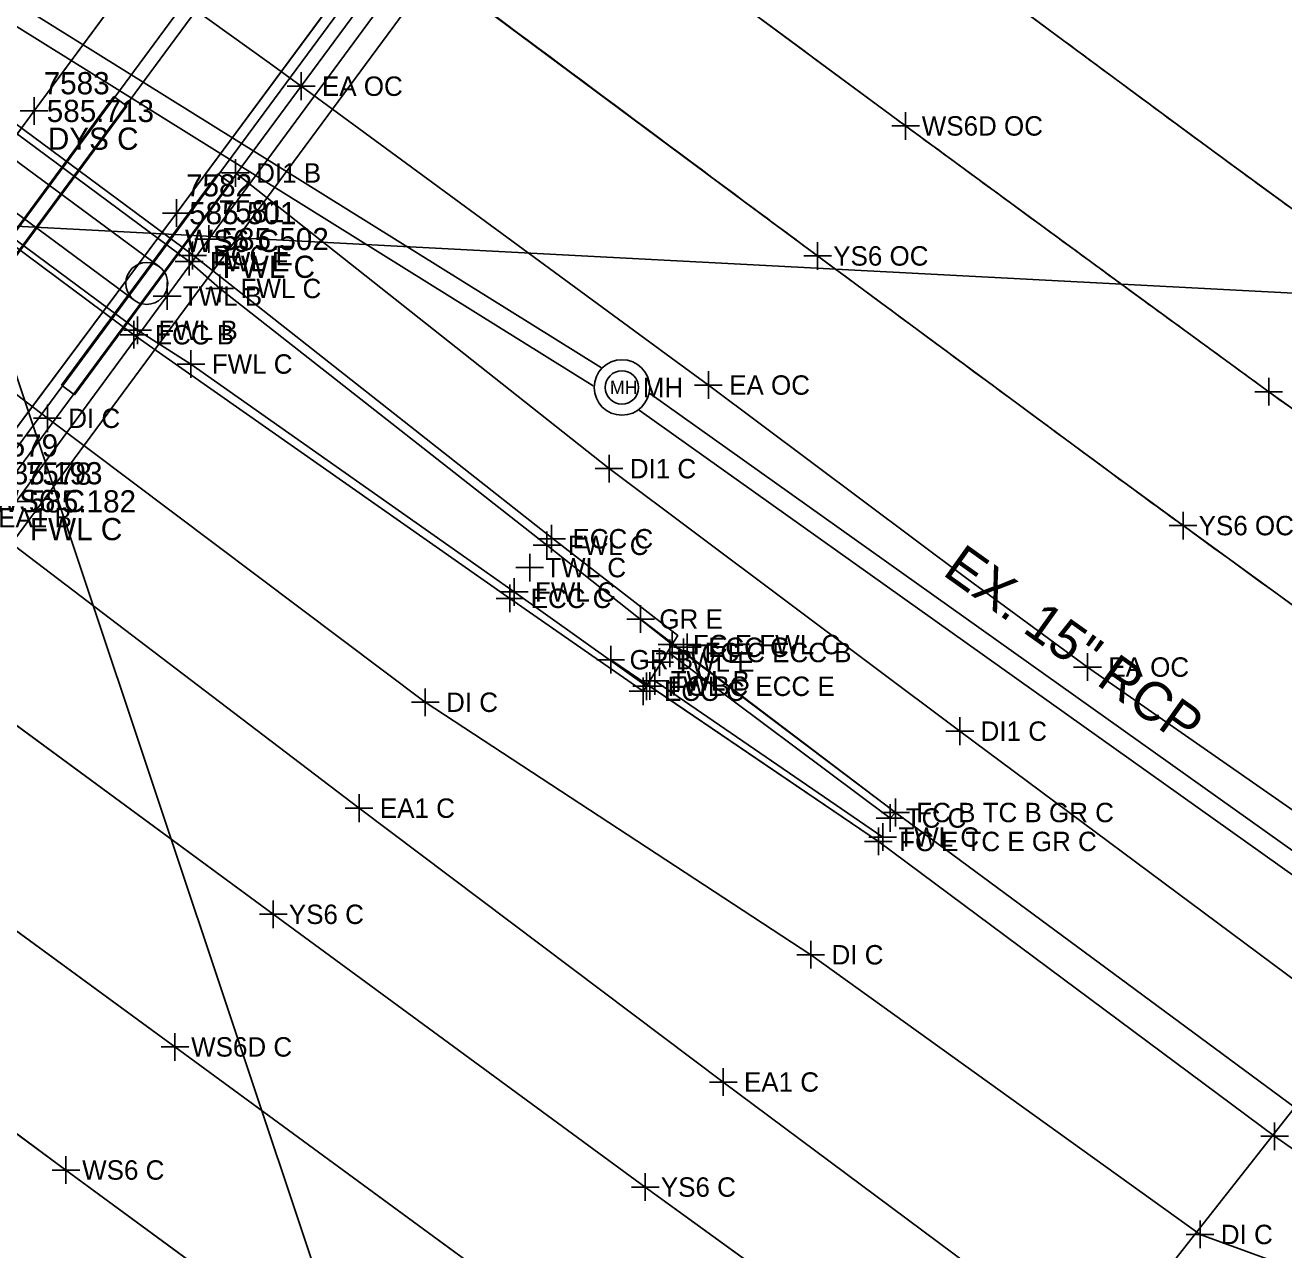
# Model space of a CAD drawing. Extents: x 1324236 to 1326110, y 459090 to 460782.
# Drawn here: x 1325137.7 to 1325228.5, y 459976.5 to 460064.8 of the extents above; entities that cross this region are included whole.
import ezdxf

# ---------------------------------------------------------------- set-up
doc = ezdxf.new("R2010")
doc.units = 0
for name, color, linetype in [('BD_X_Building', 7, 'Continuous'), ('BD_X_Canopy', 7, 'Continuous'), ('DR_X_Ditch', 7, 'Continuous'), ('DR_X_Drive_Pipe', 7, 'Continuous'), ('DR_X_Storm_Sewer', 7, 'Continuous'), ('DT_X_Contour_Text', 7, 'Continuous'), ('DT_X_Terrain_Boundary', 7, 'Continuous'), ('DT_X_Void', 7, 'Continuous'), ('DV_X_Property_Line', 7, 'Continuous'), ('E-RW-ODOT', 7, 'Continuous'), ('LT_X_Poles', 7, 'Continuous'), ('PM_X_Edge_Line', 7, 'Continuous'), ('PM_X_Lane_Line', 7, 'Continuous'), ('PM_X_Parking_Lot_Stall', 7, 'Continuous'), ('PV_X_Shoulder', 7, 'Continuous'), ('RD_X_Concrete_Barrier', 7, 'Continuous'), ('RW_X_CL', 7, 'Continuous'), ('RW_X_Esmt_SH', 7, 'Continuous'), ('UT_X_Gas', 7, 'Continuous'), ('UT_X_Telecom', 7, 'Continuous'), ('VG_X_Flower_Bed', 7, 'Continuous'), ('VG_X_Tree_Line_Lt', 7, 'Continuous')]:
    doc.layers.add(name, color=color, linetype=linetype)

msp = doc.modelspace()

# ---------------------------------------------------------------- linework, layer by layer
at = {"layer": 'BD_X_Building'}
for p, q in [((1325067.482, 459955.828), (1325213.75, 460153.784)), ((1325068.286, 459955.234), (1325214.554, 460153.19)), ((1325074.995, 459950.304), (1325221.27, 460148.255)), ((1325075.8, 459949.71), (1325222.074, 460147.66))]:
    msp.add_line(p, q, dxfattribs=at)
at = {"layer": 'BD_X_Canopy'}
for points in [[(1325045.611, 459932.876), (1325057.851, 459949.53), (1325064.246, 459958.184), (1325079.335, 459978.633), (1325094.378, 459999.012), (1325110.069, 460020.457), (1325125.333, 460040.949), (1325138.348, 460058.621), (1325153.722, 460079.38), (1325168.359, 460099.091), (1325182.797, 460118.646), (1325197.597, 460138.568), (1325210.747, 460156.012)], [(1325148.737, 460096.817), (1325164.239, 460084.921), (1325164.239, 460084.921), (1325170.939, 460079.893), (1325170.939, 460079.893), (1325200.178, 460058.291), (1325200.178, 460058.291), (1325201.195, 460057.542), (1325201.195, 460057.542), (1325216.328, 460046.448), (1325216.328, 460046.448), (1325227.38, 460038.385), (1325227.38, 460038.385), (1325239.571, 460029.695)], [(1325098.234, 460028.131), (1325120.972, 460011.28), (1325148.512, 459991.159), (1325175.708, 459971.231), (1325203.741, 459951.017), (1325230.098, 459931.753), (1325259.754, 459910.429), (1325314.217, 459871.975), (1325314.217, 459871.975), (1325341.705, 459852.598)]]:
    msp.add_lwpolyline(points, dxfattribs=at)
at = {"layer": 'DR_X_Ditch'}
for points in [[(1325155.492, 460106.108), (1325171.599, 460094.152), (1325171.599, 460094.152), (1325178.717, 460088.863), (1325178.717, 460088.863), (1325205.765, 460068.751), (1325205.765, 460068.751), (1325208.368, 460066.816), (1325208.368, 460066.816), (1325223.44, 460055.677), (1325223.44, 460055.677), (1325234.507, 460047.596)], [(1325154.473, 460078.072), (1325162.492, 460072.218), (1325162.492, 460072.218), (1325164.488, 460070.746), (1325164.488, 460070.746), (1325189.586, 460052.08), (1325189.586, 460052.08), (1325194.852, 460048.172), (1325194.852, 460048.172), (1325216.033, 460032.518), (1325216.033, 460032.518), (1325221.2, 460028.735), (1325221.2, 460028.735), (1325230.11, 460022.268)], [(1325105.01, 460038.085), (1325127.697, 460021.23), (1325155.597, 460000.717), (1325182.421, 459981.058), (1325210.568, 459960.686), (1325238.635, 459940.347), (1325308.698, 459890.503), (1325308.698, 459890.503), (1325349.012, 459862.044), (1325349.012, 459862.044), (1325431.768, 459803.914), (1325432.23, 459803.591), (1325432.23, 459803.591), (1325448.949, 459791.987), (1325448.949, 459791.987), (1325460.04, 459784.342), (1325460.04, 459784.342), (1325460.306, 459784.16), (1325460.306, 459784.16), (1325516.924, 459745.667), (1325550.103, 459723.204), (1325550.103, 459723.204), (1325604.669, 459686.509)], [(1325091.366, 460018.476), (1325114.182, 460001.814), (1325140.652, 459982.287), (1325168.982, 459961.472), (1325196.796, 459941.357), (1325224.067, 459921.485), (1325251.917, 459901.296), (1325270.427, 459887.921), (1325270.427, 459887.921), (1325279.777, 459881.226), (1325279.777, 459881.226), (1325307.114, 459861.771), (1325307.435, 459861.543), (1325307.435, 459861.543), (1325324.586, 459849.365), (1325324.586, 459849.365), (1325334.901, 459842.056), (1325334.901, 459842.056), (1325346.757, 459833.744)]]:
    msp.add_lwpolyline(points, dxfattribs=at)
at = {"layer": 'DR_X_Drive_Pipe'}
for p, q in [((1325116.434, 460053.941), (1325139.317, 460036.47)), ((1325152.869, 460054.151), (1325179.808, 460032.838)), ((1325139.317, 460036.47), (1325166.561, 460016.001)), ((1325179.808, 460032.838), (1325205.103, 460013.92)), ((1325166.561, 460016.001), (1325194.355, 459997.801)), ((1325205.103, 460013.92), (1325233.712, 459992.633)), ((1325194.355, 459997.801), (1325222.428, 459977.642)), ((1325222.428, 459977.642), (1325255.046, 459965.693))]:
    msp.add_line(p, q, dxfattribs=at)
at = {"layer": 'DR_X_Storm_Sewer'}
for p, q in [((1325138.348, 460058.621), (1325153.722, 460079.38)), ((1325125.333, 460040.949), (1325138.348, 460058.621))]:
    msp.add_line(p, q, dxfattribs=at)
at = {"layer": 'DT_X_Contour_Text'}
for p, q in [((1325150.954, 460049.389), (1325166.209, 460070.056)), ((1325137.054, 460030.482), (1325150.954, 460049.389))]:
    msp.add_line(p, q, dxfattribs=at)
at = {"layer": 'DT_X_Terrain_Boundary'}
for p, q in [((1325124.57, 460066.249), (1325149.534, 460047.765)), ((1325145.557, 460042.49), (1325120.636, 460060.99)), ((1325145.819, 460042.81), (1325120.894, 460061.298)), ((1325151.741, 460045.827), (1325149.534, 460047.765)), ((1325175.332, 460027.312), (1325151.741, 460045.827)), ((1325145.819, 460042.81), (1325149.662, 460040.381)), ((1325145.557, 460042.49), (1325172.66, 460023.49)), ((1325149.662, 460040.381), (1325172.972, 460023.953)), ((1325184.364, 460020.16), (1325175.332, 460027.312)), ((1325172.972, 460023.953), (1325182.518, 460017.154)), ((1325172.66, 460023.49), (1325182.272, 460016.797)), ((1325182.518, 460017.154), (1325184.364, 460020.16)), ((1325185.185, 460019.586), (1325184.364, 460020.16)), ((1325200.078, 460007.655), (1325184.206, 460019.521)), ((1325200.465, 460008.054), (1325185.185, 460019.586)), ((1325183.124, 460017.545), (1325199.545, 460006.288)), ((1325182.272, 460016.797), (1325182.518, 460017.154)), ((1325182.749, 460017.171), (1325199.229, 460005.968)), ((1325200.465, 460008.054), (1325200.078, 460007.655))]:
    msp.add_line(p, q, dxfattribs=at)
msp.add_lwpolyline([(1325184.337, 460020.14), (1325184.771, 460020.802), (1325175.691, 460027.851), (1325149.757, 460048.271), (1325124.75, 460066.799), (1325087.999, 460092.157), (1325087.726, 460091.756)], dxfattribs=at)
at = {"layer": 'DV_X_Property_Line'}
for p, q in [((1325157.61, 460059.405), (1325157.61, 460061.405)), ((1325156.61, 460060.405), (1325158.61, 460060.405)), ((1325150.954, 460048.389), (1325150.954, 460050.389)), ((1325149.78, 460047.202), (1325149.78, 460049.202)), ((1325149.954, 460049.389), (1325151.954, 460049.389)), ((1325148.78, 460048.202), (1325150.78, 460048.202)), ((1325149.534, 460046.765), (1325149.534, 460048.765)), ((1325148.534, 460047.765), (1325150.534, 460047.765)), ((1325147.947, 460044.282), (1325147.947, 460046.282)), ((1325151.741, 460044.827), (1325151.741, 460046.827)), ((1325150.741, 460045.827), (1325152.741, 460045.827)), ((1325146.947, 460045.282), (1325148.947, 460045.282)), ((1325145.819, 460041.81), (1325145.819, 460043.81)), ((1325144.819, 460042.81), (1325146.819, 460042.81)), ((1325145.557, 460041.49), (1325145.557, 460043.49)), ((1325144.557, 460042.49), (1325146.557, 460042.49)), ((1325149.662, 460039.381), (1325149.662, 460041.381)), ((1325148.662, 460040.381), (1325150.662, 460040.381)), ((1325186.973, 460037.864), (1325186.973, 460039.864)), ((1325185.973, 460038.864), (1325187.973, 460038.864)), ((1325136.054, 460030.482), (1325138.054, 460030.482)), ((1325175.332, 460026.312), (1325175.332, 460028.312)), ((1325175.669, 460026.788), (1325175.669, 460028.788)), ((1325174.332, 460027.312), (1325176.332, 460027.312)), ((1325174.669, 460027.788), (1325176.669, 460027.788)), ((1325174.09, 460024.709), (1325174.09, 460026.709)), ((1325173.09, 460025.709), (1325175.09, 460025.709)), ((1325172.66, 460022.49), (1325172.66, 460024.49)), ((1325172.972, 460022.953), (1325172.972, 460024.953)), ((1325171.972, 460023.953), (1325173.972, 460023.953)), ((1325171.66, 460023.49), (1325173.66, 460023.49)), ((1325184.364, 460019.16), (1325184.364, 460021.16)), ((1325185.451, 460018.964), (1325185.451, 460020.964)), ((1325183.364, 460020.16), (1325185.364, 460020.16)), ((1325184.206, 460018.521), (1325184.206, 460020.521)), ((1325184.451, 460019.964), (1325186.451, 460019.964)), ((1325185.185, 460018.586), (1325185.185, 460020.586)), ((1325183.206, 460019.521), (1325185.206, 460019.521)), ((1325183.448, 460017.898), (1325183.448, 460019.898)), ((1325184.185, 460019.586), (1325186.185, 460019.586)), ((1325214.311, 460017.539), (1325214.311, 460019.539)), ((1325182.448, 460018.898), (1325184.448, 460018.898)), ((1325182.518, 460016.154), (1325182.518, 460018.154)), ((1325182.749, 460016.171), (1325182.749, 460018.171)), ((1325183.124, 460016.545), (1325183.124, 460018.545)), ((1325213.311, 460018.539), (1325215.311, 460018.539)), ((1325182.124, 460017.545), (1325184.124, 460017.545)), ((1325182.272, 460015.797), (1325182.272, 460017.797)), ((1325181.272, 460016.797), (1325183.272, 460016.797)), ((1325181.518, 460017.154), (1325183.518, 460017.154)), ((1325181.749, 460017.171), (1325183.749, 460017.171)), ((1325161.787, 460007.367), (1325161.787, 460009.367)), ((1325200.465, 460007.054), (1325200.465, 460009.054)), ((1325160.787, 460008.367), (1325162.787, 460008.367)), ((1325200.078, 460006.655), (1325200.078, 460008.655)), ((1325199.078, 460007.655), (1325201.078, 460007.655)), ((1325199.465, 460008.054), (1325201.465, 460008.054)), ((1325199.545, 460005.288), (1325199.545, 460007.288)), ((1325199.229, 460004.968), (1325199.229, 460006.968)), ((1325198.229, 460005.968), (1325200.229, 460005.968)), ((1325198.545, 460006.288), (1325200.545, 460006.288)), ((1325188.044, 459987.629), (1325188.044, 459989.629)), ((1325187.044, 459988.629), (1325189.044, 459988.629))]:
    msp.add_line(p, q, dxfattribs=at)
at = {"layer": 'E-RW-ODOT'}
for p, q in [((1325084.273, 460197.503), (1325176.946, 459920.265)), ((1325176.946, 459920.265), (1325084.273, 460197.503)), ((1325006.97, 460057.154), (1325273.546, 460043.161)), ((1325273.546, 460043.161), (1325176.946, 459920.265))]:
    msp.add_line(p, q, dxfattribs=at)
at = {"layer": 'LT_X_Poles'}
for points in [[(1325155.492, 460106.108), (1325171.599, 460094.152), (1325171.599, 460094.152), (1325178.717, 460088.863), (1325178.717, 460088.863), (1325205.765, 460068.751), (1325205.765, 460068.751), (1325208.368, 460066.816), (1325208.368, 460066.816), (1325223.44, 460055.677), (1325223.44, 460055.677), (1325234.507, 460047.596)], [(1325154.473, 460078.072), (1325162.492, 460072.218), (1325162.492, 460072.218), (1325164.488, 460070.746), (1325164.488, 460070.746), (1325189.586, 460052.08), (1325189.586, 460052.08), (1325194.852, 460048.172), (1325194.852, 460048.172), (1325216.033, 460032.518), (1325216.033, 460032.518), (1325221.2, 460028.735), (1325221.2, 460028.735), (1325230.11, 460022.268)], [(1325105.01, 460038.085), (1325127.697, 460021.23), (1325155.597, 460000.717), (1325182.421, 459981.058), (1325210.568, 459960.686), (1325238.635, 459940.347), (1325308.698, 459890.503), (1325308.698, 459890.503), (1325349.012, 459862.044), (1325349.012, 459862.044), (1325431.768, 459803.914), (1325432.23, 459803.591), (1325432.23, 459803.591), (1325448.949, 459791.987), (1325448.949, 459791.987), (1325460.04, 459784.342), (1325460.04, 459784.342), (1325460.306, 459784.16), (1325460.306, 459784.16), (1325516.924, 459745.667), (1325550.103, 459723.204), (1325550.103, 459723.204), (1325604.669, 459686.509)]]:
    msp.add_lwpolyline(points, dxfattribs=at)
at = {"layer": 'PM_X_Edge_Line'}
for p, q in [((1325148.617, 460051.256), (1325163.849, 460071.849)), ((1325134.634, 460032.509), (1325148.617, 460051.256)), ((1325127.697, 460021.23), (1325155.597, 460000.717)), ((1325114.182, 460001.814), (1325140.652, 459982.287)), ((1325155.597, 460000.717), (1325182.421, 459981.058)), ((1325140.652, 459982.287), (1325168.982, 459961.472)), ((1325182.421, 459981.058), (1325210.568, 459960.686))]:
    msp.add_line(p, q, dxfattribs=at)
msp.add_lwpolyline([(1325043.875, 459908.523), (1325057.387, 459928.027), (1325068.015, 459942.962), (1325074.036, 459951.056), (1325089.476, 459972.013), (1325104.352, 459991.824), (1325119.711, 460012.415), (1325134.634, 460032.509), (1325148.617, 460051.256), (1325163.849, 460071.849), (1325178.331, 460091.329), (1325192.857, 460110.836), (1325207.605, 460130.872), (1325220.672, 460148.677), (1325238.037, 460172.457)], dxfattribs=at)
for centre, radius, start, end in [((1288412.388, 410628.623), 61605.523, 53.34616686, 53.37525632), ((1327520.448, 463179.43), 3877.38, 233.394682, 233.671626), ((1326451.382, 461725.584), 2072.783, 233.671626, 234.050404), ((1326806.58, 462225.097), 2708.629, 233.346168, 233.484897), ((1334204.095, 472216.755), 15140.702, 233.4848971, 233.5845657), ((1325747.372, 460752.802), 895.058, 233.584566, 233.994493), ((1331359.526, 468475.708), 10441.763, 233.9944926, 234.054904)]:
    msp.add_arc(centre, radius, start, end, dxfattribs=at)
at = {"layer": 'PM_X_Lane_Line'}
for p, q in [((1325120.972, 460011.28), (1325148.512, 459991.159)), ((1325148.512, 459991.159), (1325175.708, 459971.231))]:
    msp.add_line(p, q, dxfattribs=at)
for centre, radius, start, end in [((1556801.847, 773572.451), 389782.583, 233.54033854, 233.54568232), ((1325479.679, 460436.645), 470.396, 233.54569, 233.69951), ((1330948.154, 467880.94), 9707.373, 233.6995143, 233.8102652), ((1328263.033, 464210.807), 5159.874, 233.810265, 233.962173), ((1325681.602, 460662.701), 772.068, 233.962173, 235.073227)]:
    msp.add_arc(centre, radius, start, end, dxfattribs=at)
at = {"layer": 'PM_X_Parking_Lot_Stall'}
for p, q in [((1325200.465, 460008.054), (1325182.082, 460021.998)), ((1325179.935, 460019.067), (1325199.229, 460005.968)), ((1325229.8, 459986.398), (1325200.465, 460008.054)), ((1325199.229, 460005.968), (1325227.798, 459984.715)), ((1325227.798, 459984.715), (1325232.556, 459981.38))]:
    msp.add_line(p, q, dxfattribs=at)
at = {"layer": 'PV_X_Shoulder'}
for p, q in [((1325132.825, 460044.397), (1325144.101, 460059.657)), ((1325145.034, 460058.968), (1325133.758, 460043.708)), ((1325145.034, 460058.968), (1325144.101, 460059.657)), ((1325140.333, 460038.858), (1325151.594, 460054.098)), ((1325152.527, 460053.409), (1325151.594, 460054.098)), ((1325152.527, 460053.409), (1325141.266, 460038.169)), ((1325141.266, 460038.169), (1325140.333, 460038.858))]:
    msp.add_line(p, q, dxfattribs=at)
for points in [[(1325146.82, 460068.183), (1325155.308, 460062.079), (1325155.308, 460062.079), (1325157.61, 460060.405), (1325157.61, 460060.405), (1325184.297, 460040.83), (1325184.297, 460040.83), (1325186.973, 460038.864), (1325186.973, 460038.864), (1325205.601, 460024.932), (1325205.601, 460024.932), (1325214.311, 460018.539), (1325214.311, 460018.539), (1325218.921, 460015.3), (1325218.921, 460015.3), (1325239.182, 460001.215)], [(1325111.268, 460046.593), (1325134.264, 460029.301), (1325161.787, 460008.367), (1325188.044, 459988.629), (1325215.708, 459968.019), (1325243.741, 459947.203), (1325271.41, 459926.585), (1325325.349, 459887.247), (1325325.349, 459887.247), (1325352.997, 459867.035)]]:
    msp.add_lwpolyline(points, dxfattribs=at)
at = {"layer": 'RD_X_Concrete_Barrier'}
for radius in [2, 1.2]:
    msp.add_circle((1325180.741, 460038.69), radius, dxfattribs=at)
at = {"layer": 'RW_X_CL'}
for p, q in [((1325138.348, 460057.621), (1325138.348, 460059.621)), ((1325137.348, 460058.621), (1325139.348, 460058.621)), ((1325201.195, 460056.542), (1325201.195, 460058.542)), ((1325200.195, 460057.542), (1325202.195, 460057.542)), ((1325152.869, 460053.151), (1325152.869, 460055.151)), ((1325151.869, 460054.151), (1325153.869, 460054.151)), ((1325148.617, 460050.256), (1325148.617, 460052.256)), ((1325147.617, 460051.256), (1325149.617, 460051.256)), ((1325194.852, 460047.172), (1325194.852, 460049.172)), ((1325193.852, 460048.172), (1325195.852, 460048.172)), ((1325227.38, 460037.385), (1325227.38, 460039.385)), ((1325226.38, 460038.385), (1325228.38, 460038.385)), ((1325179.808, 460031.838), (1325179.808, 460033.838)), ((1325178.808, 460032.838), (1325180.808, 460032.838)), ((1325221.2, 460027.735), (1325221.2, 460029.735)), ((1325220.2, 460028.735), (1325222.2, 460028.735)), ((1325205.103, 460012.92), (1325205.103, 460014.92)), ((1325204.103, 460013.92), (1325206.103, 460013.92)), ((1325155.597, 459999.717), (1325155.597, 460001.717)), ((1325154.597, 460000.717), (1325156.597, 460000.717)), ((1325148.512, 459990.159), (1325148.512, 459992.159)), ((1325147.512, 459991.159), (1325149.512, 459991.159)), ((1325140.652, 459981.287), (1325140.652, 459983.287)), ((1325139.652, 459982.287), (1325141.652, 459982.287)), ((1325182.421, 459980.058), (1325182.421, 459982.058)), ((1325181.421, 459981.058), (1325183.421, 459981.058))]:
    msp.add_line(p, q, dxfattribs=at)
at = {"layer": 'RW_X_Esmt_SH'}
for p, q in [((1325139.317, 460035.47), (1325139.317, 460037.47)), ((1325138.317, 460036.47), (1325140.317, 460036.47)), ((1325182.082, 460020.998), (1325182.082, 460022.998)), ((1325181.082, 460021.998), (1325183.082, 460021.998)), ((1325179.935, 460018.067), (1325179.935, 460020.067)), ((1325178.935, 460019.067), (1325180.935, 460019.067)), ((1325166.561, 460015.001), (1325166.561, 460017.001)), ((1325165.561, 460016.001), (1325167.561, 460016.001)), ((1325194.355, 459996.801), (1325194.355, 459998.801)), ((1325193.355, 459997.801), (1325195.355, 459997.801)), ((1325227.798, 459983.715), (1325227.798, 459985.715)), ((1325226.798, 459984.715), (1325228.798, 459984.715)), ((1325222.428, 459976.642), (1325222.428, 459978.642)), ((1325221.428, 459977.642), (1325223.428, 459977.642))]:
    msp.add_line(p, q, dxfattribs=at)
at = {"layer": 'UT_X_Gas'}
msp.add_line((1325078.063, 459948.049), (1325224.327, 460146.007), dxfattribs=at)
at = {"layer": 'VG_X_Flower_Bed'}
for p, q in [((1325179.267, 460040.1), (1325032.782, 460131.415)), ((1325178.666, 460038.796), (1325032.157, 460130.12)), ((1325443.071, 459853.124), (1325182.751, 460038.25)), ((1325442.281, 459851.941), (1325181.982, 460037.043))]:
    msp.add_line(p, q, dxfattribs=at)
at = {"layer": 'VG_X_Tree_Line_Lt'}
for p, q in [((1325147.374, 460047.404), (1325124.846, 460064.049)), ((1325123.052, 460061.621), (1325145.579, 460044.975))]:
    msp.add_line(p, q, dxfattribs=at)
msp.add_circle((1325146.477, 460046.19), 1.51, dxfattribs=at)

# ---------------------------------------------------------------- texts
at = {"layer": 'DT_X_Void'}
msp.add_text('MH', height=1.4, dxfattribs=at).set_placement((1325182.241, 460037.99))
at = {"layer": 'DV_X_Property_Line'}
for s, height, p in [('EA OC', 1.4, (1325159.11, 460059.705)), ('7581', 1.6, (1325151.649, 460050.589)), ('585.502', 1.6, (1325151.872, 460048.589)), ('FWL E', 1.4, (1325151.034, 460047.065)), ('ECC E', 1.4, (1325151.28, 460047.502)), ('FWL C', 1.6, (1325151.954, 460046.589)), ('FWL C', 1.4, (1325153.241, 460045.127)), ('TWL B', 1.4, (1325149.072, 460044.582)), ('FWL B', 1.4, (1325147.319, 460042.11)), ('ECC B', 1.4, (1325147.057, 460041.79)), ('FWL C', 1.4, (1325151.162, 460039.681)), ('EA OC', 1.4, (1325188.473, 460038.164)), ('7578', 1.6, (1325137.749, 460031.682)), ('585.182', 1.6, (1325137.972, 460029.682)), ('EA1 B', 1.4, (1325135.764, 460028.601)), ('FWL C', 1.6, (1325138.054, 460027.682)), ('ECC C', 1.4, (1325177.169, 460027.088)), ('FWL C', 1.4, (1325176.832, 460026.612)), ('TWL C', 1.4, (1325175.215, 460025.009)), ('FWL C', 1.4, (1325174.472, 460023.253)), ('ECC C', 1.4, (1325174.16, 460022.79)), ('FC E FWL C', 1.4, (1325185.864, 460019.46)), ('TC E', 1.4, (1325185.331, 460018.821)), ('FC C ECC B', 1.4, (1325186.685, 460018.886)), ('ECC C', 1.4, (1325186.951, 460019.264)), ('TWL E', 1.4, (1325184.573, 460018.198)), ('EA OC', 1.4, (1325215.811, 460017.839)), ('TWL B', 1.4, (1325184.249, 460016.845)), ('ECC C', 1.4, (1325183.772, 460016.097)), ('FWL C ECC E', 1.4, (1325184.018, 460016.454)), ('FC B', 1.4, (1325184.249, 460016.471)), ('EA1 C', 1.4, (1325163.287, 460007.667)), ('TC C', 1.4, (1325201.203, 460006.955)), ('FC B TC B GR C', 1.4, (1325201.965, 460007.354)), ('TWL C', 1.4, (1325200.67, 460005.588)), ('FC E TC E GR C', 1.4, (1325200.729, 460005.268)), ('EA1 C', 1.4, (1325189.544, 459987.929))]:
    msp.add_text(s, height=height, dxfattribs=at).set_placement(p)
at = {"layer": 'RD_X_Concrete_Barrier'}
msp.add_text('MH', height=0.96, dxfattribs=at).set_placement((1325179.873, 460038.21))
at = {"layer": 'RW_X_CL'}
for s, height, p in [('7583', 1.6, (1325139.043, 460059.821)), ('585.713', 1.6, (1325139.266, 460057.821)), ('WS6D OC', 1.4, (1325202.362, 460056.842)), ('DYS C', 1.6, (1325139.348, 460055.821)), ('DI1 B', 1.4, (1325154.369, 460053.451)), ('7582', 1.6, (1325149.312, 460052.456)), ('585.501', 1.6, (1325149.535, 460050.456)), ('WS6 C', 1.6, (1325149.236, 460048.456)), ('YS6 OC', 1.4, (1325195.977, 460047.472)), ('7579', 1.6, (1325135.329, 460033.709)), ('DI1 C', 1.4, (1325181.308, 460032.138)), ('585.193', 1.6, (1325135.552, 460031.709)), ('WS6 C', 1.6, (1325135.253, 460029.709)), ('YS6 OC', 1.4, (1325222.325, 460028.035)), ('DI1 C', 1.4, (1325206.603, 460013.22)), ('YS6 C', 1.4, (1325156.722, 460000.017)), ('WS6D C', 1.4, (1325149.679, 459990.459)), ('WS6 C', 1.4, (1325141.819, 459981.587)), ('YS6 C', 1.4, (1325183.546, 459980.358))]:
    msp.add_text(s, height=height, dxfattribs=at).set_placement(p)
at = {"layer": 'RW_X_Esmt_SH'}
for s, p in [('DI C', (1325140.817, 460035.77)), ('GR E', (1325183.439, 460021.298)), ('GR B', (1325181.292, 460018.367)), ('DI C', (1325168.061, 460015.301)), ('DI C', (1325195.855, 459997.101)), ('DI C', (1325223.928, 459976.942))]:
    msp.add_text(s, height=1.4, dxfattribs=at).set_placement(p)
at = {"layer": 'UT_X_Telecom'}
msp.add_text('EX. 15" RCP', height=2.79999, rotation=324.52859, dxfattribs=at).set_placement((1325203.78, 460025.231))

doc.saveas('drawing.dxf')
